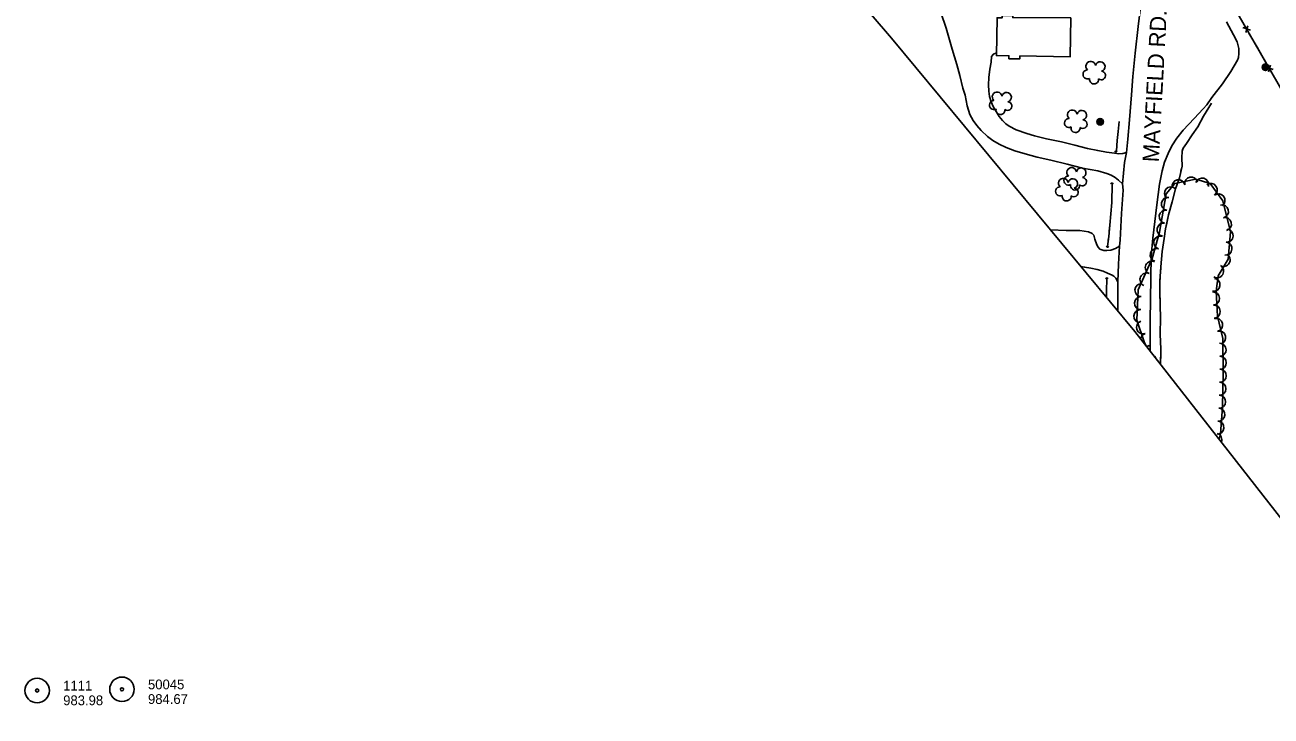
# Model space of a CAD drawing. Extents: x 353423 to 364002, y 127000 to 201942.
# Drawn here: x 356703 to 357469, y 134404 to 134829 of the extents above; entities that cross this region are included whole.
import ezdxf

# ---------------------------------------------------------------- set-up
doc = ezdxf.new("R2010")
doc.units = 0
for name, color, linetype in [('E_DTM_SlopeBottom', 7, 'Continuous'), ('E_DTM_SlopeTop', 7, 'Continuous'), ('E_FEN_Generic', 7, 'Continuous'), ('E_LAND_BrushLine', 7, 'Continuous'), ('E_MISCPROP', 7, 'Continuous'), ('E_RDWY_AsphConc', 7, 'Continuous'), ('E_RDWY_Gravel', 7, 'Continuous'), ('E_RW_IP', 7, 'Continuous'), ('E_STRUCT_WingWall', 7, 'Continuous'), ('E_WTR_FlowLine', 7, 'Continuous')]:
    doc.layers.add(name, color=color, linetype=linetype)

msp = doc.modelspace()

# ---------------------------------------------------------------- linework, layer by layer
at = {"layer": 'E_DTM_SlopeBottom'}
for p, q in [((357456.04, 134825.55), (357451.37, 134827.15)), ((357453.14, 134824.08), (357454.49, 134828.08)), ((357469.96, 134801.42), (357465.3, 134803.02)), ((357467.07, 134799.95), (357468.42, 134803.95))]:
    msp.add_line(p, q, dxfattribs=at)
for points in [[(357746.81, 134404.35), (357704.25, 134463.37), (357646.07, 134541.07), (357599.43, 134604.83), (357559.68, 134657.67), (357521.7, 134708.64), (357480.05, 134780.45), (357448.29, 134835.48), (357398.42, 134896.02), (357357.23, 134944.19), (357299.64, 135012.53), (357238.04, 135085.86), (357191.74, 135137.71), (357148.42, 135186.77), (357116.33, 135222.96), (357071.29, 135272.31), (357040.14, 135306.75), (357007.93, 135341.38)], [(357460.09, 134815.05), (357455.11, 134823.67)], [(357465.74, 134805.24), (357460.09, 134815.05)]]:
    msp.add_lwpolyline(points, dxfattribs=at)
for centre, major_axis, ratio, start_param, end_param in [((357373.66, 134752.11), (-0.34, -1.28), 0.626074, 5.356084, 7.210314), ((357370.83, 134730.28), (0.23, 1.35), 0.716546, 5.356056, 7.210287), ((357368.37, 134693.69), (-0.2, -1.41), 0.672824, 5.356084, 7.210314), ((357367.77, 134671.83), (0.08, 1.63), 0.539577, 5.356084, 7.210314)]:
    msp.add_ellipse(centre, major_axis=major_axis, ratio=ratio, start_param=start_param, end_param=end_param, dxfattribs=at)
at = {"layer": 'E_DTM_SlopeTop'}
for points in [[(357388.44, 134839.57), (357387.01, 134827.75), (357385.26, 134811.36), (357383.89, 134797.14), (357383.02, 134785.85), (357381.71, 134770.52), (357380.73, 134758.61), (357379.93, 134750.33), (357378.74, 134744.21), (357377.49, 134731.14), (357377.84, 134727.25), (357376.93, 134712.94), (357376.04, 134696.53), (357375.7, 134692.9), (357375.11, 134681.73), (357374.5, 134671), (357374.53, 134657.79), (357374.5, 134653.13)], [(357394.56, 134628.26), (357394.56, 134646.97), (357394.85, 134673.44), (357395.03, 134686.65), (357396.02, 134697.78), (357398.46, 134718.24), (357400.12, 134730.92), (357401.78, 134739.22), (357403.28, 134744.43), (357405.49, 134749.82), (357407.76, 134754.47), (357410.78, 134759.3), (357414.83, 134764.11), (357421.54, 134771.25), (357427.03, 134777.3), (357429.2, 134779.6), (357432.33, 134784.26), (357438.79, 134792.56), (357443.95, 134800.19), (357448.09, 134807.18), (357448.76, 134808.78), (357448.94, 134811.13), (357448.9, 134814.31), (357447.85, 134818.26), (357445.73, 134822.57), (357441.4, 134830.7)]]:
    msp.add_lwpolyline(points, dxfattribs=at)
at = {"layer": 'E_FEN_Generic'}
msp.add_lwpolyline([(357436.74, 134574.36), (357437.64, 134577.73), (357438.82, 134594.3), (357439.37, 134615.35), (357439.17, 134636.18), (357435.82, 134649.89), (357434.9, 134665.2), (357436.3, 134674.58), (357442.28, 134685), (357443.71, 134701.65), (357439.17, 134720.77), (357431.27, 134731.46), (357422.42, 134734.09), (357409.54, 134731.29), (357404.26, 134724.99), (357400.25, 134701.47), (357395.69, 134685.23), (357387.01, 134666.13), (357386.27, 134647.4), (357390.8, 134634.14), (357392.22, 134631.26)], dxfattribs=at)
for centre, radius, start, end in [((357357.94, 134803.37), 2.97, 7.26141, 228.49529), ((357363.79, 134803.14), 2.97, 284.91223, 167.8855), ((357355.98, 134798.36), 2.78, 90.2323, 298.00529), ((357360, 134795.28), 2.78, 166.90931, 7.92036), ((357364.45, 134797.65), 2.61, 229.61746, 87.55007), ((357300.45, 134784.56), 2.97, 7.26141, 228.49529), ((357306.3, 134784.33), 2.97, 284.91223, 167.8855), ((357298.49, 134779.56), 2.78, 90.2323, 298.00529), ((357306.95, 134778.85), 2.61, 229.61746, 87.55007), ((357302.51, 134776.47), 2.78, 166.90931, 7.92036), ((357344.63, 134768.51), 2.78, 90.2323, 298.00529), ((357346.59, 134773.51), 2.97, 7.26141, 228.49529), ((357352.43, 134773.29), 2.97, 284.91223, 167.8855), ((357348.64, 134765.43), 2.78, 166.90931, 7.92036), ((357353.09, 134767.8), 2.61, 229.61746, 87.55007), ((357346.23, 134738.17), 2.97, 7.26141, 228.49529), ((357352.08, 134737.94), 2.97, 284.91223, 167.8855), ((357341.1, 134731.53), 2.97, 7.26141, 228.49529), ((357344.27, 134733.16), 2.78, 90.2323, 298.00529), ((357346.95, 134731.3), 2.97, 284.91223, 167.8855), ((357352.74, 134732.46), 2.61, 229.61746, 87.55007), ((357411.85, 134729.65), 4, 12.27553, 192.2602), ((357419.67, 134731.35), 4, 12.27553, 192.2602), ((357426.36, 134730.74), 4, 343.47008, 163.45476), ((357339.14, 134726.53), 2.78, 90.2323, 298.00529), ((357348.29, 134730.08), 2.78, 166.90931, 7.92036), ((357347.61, 134725.82), 2.61, 229.61746, 87.55007), ((357407.23, 134725.28), 4, 50.02031, 230.00499), ((357431.66, 134727.41), 4, 306.43791, 126.42258), ((357343.16, 134723.44), 2.78, 166.90931, 7.92036), ((357405.34, 134718.86), 4, 80.34236, 260.32704), ((357436.41, 134720.97), 4, 306.43791, 126.42258), ((357438.56, 134714.26), 4, 283.35437, 103.33905), ((357403.99, 134710.97), 4, 80.34236, 260.32704), ((357440.41, 134706.47), 4, 283.35437, 103.33905), ((357402.65, 134703.09), 4, 80.34236, 260.32704), ((357441.4, 134699.29), 4, 265.10079, 85.08547), ((357400.65, 134695.13), 4, 74.32817, 254.31285), ((357440.72, 134691.32), 4, 265.10079, 85.08547), ((357398.48, 134687.43), 4, 74.32817, 254.31285), ((357439.55, 134684.45), 4, 240.17306, 60.15774), ((357395.48, 134679.69), 4, 65.56841, 245.55309), ((357435.57, 134677.51), 4, 240.17306, 60.15774), ((357392.17, 134672.41), 4, 65.56841, 245.55309), ((357433.37, 134669.13), 4, 261.49924, 81.48392), ((357389.1, 134665.9), 4, 87.74334, 267.72802), ((357433.07, 134660.75), 4, 273.44352, 93.4282), ((357388.78, 134657.91), 4, 87.74334, 267.72802), ((357433.55, 134652.76), 4, 273.44352, 93.4282), ((357388.47, 134649.91), 4, 87.74334, 267.72802), ((357390, 134642.96), 4, 108.85885, 288.84352), ((357434.97, 134644.54), 4, 283.75563, 103.74031), ((357392.58, 134635.39), 4, 108.85885, 173.19028), ((357436.87, 134636.77), 4, 283.75563, 103.74031), ((357392.58, 134635.39), 4, 262.89689, 288.84353), ((357395.86, 134628.61), 4, 121.46991, 146.02388), ((357437.15, 134629.28), 4, 270.54592, 90.53059), ((357395.86, 134628.61), 4, 290.06329, 301.45459), ((357400.03, 134621.79), 4, 121.46991, 132.60292), ((357437.22, 134621.28), 4, 270.54592, 90.53059), ((357437.22, 134613.36), 4, 268.50051, 88.48519), ((357437.01, 134605.36), 4, 268.50051, 88.48519), ((357436.8, 134597.37), 4, 268.50051, 88.48519), ((357436.37, 134589.48), 4, 265.93674, 85.92142), ((357435.81, 134581.5), 4, 265.93674, 85.92142), ((357434.49, 134574.04), 4, 337.48606, 75.15008)]:
    msp.add_arc(centre, radius, start, end, dxfattribs=at)
at = {"layer": 'E_LAND_BrushLine'}
for centre, radius in [((357465.22, 134802.73), 2.02), ((357465.2, 134802.72), 1.52), ((357465.24, 134802.73), 1.01), ((357465.23, 134802.73), 0.502), ((357363.68, 134769.26), 2.02), ((357363.67, 134769.25), 1.52), ((357363.71, 134769.26), 1.01), ((357363.7, 134769.26), 0.502)]:
    msp.add_circle(centre, radius, dxfattribs=at)
at = {"layer": 'E_MISCPROP'}
for points in [[(357265.85, 134836.31), (357269.19, 134826.84), (357272.85, 134813.82), (357275.62, 134804.49), (357277.55, 134797.63), (357279.49, 134789.94), (357280.74, 134785.53), (357282.05, 134778.96), (357283.61, 134773.64), (357285.7, 134769.99), (357287.9, 134767.04), (357290.58, 134763.91), (357294.49, 134760.3), (357297.73, 134757.86), (357301.76, 134755.61), (357306.08, 134753.47), (357311.4, 134751.43), (357317.75, 134749.61), (357325.14, 134747.6), (357333.47, 134745.6), (357343.56, 134743.15), (357352.92, 134740.8), (357362.33, 134739.14), (357367.87, 134737.55), (357370.57, 134736.57), (357373.05, 134735.14), (357375.11, 134733.4), (357377.49, 134731.14)], [(357379.93, 134750.33), (357377.57, 134749.81), (357375.13, 134749.67), (357372.61, 134749.94), (357367.72, 134750.57), (357362.25, 134751.58), (357355.96, 134752.86), (357348.25, 134754.96), (357339.96, 134756.87), (357330.84, 134758.81), (357323.45, 134760.57), (357318.66, 134762.02), (357312.11, 134764.38), (357307.88, 134766.64), (357305.81, 134768.1), (357303.79, 134770.09), (357301.75, 134772.58), (357299.77, 134775.48), (357298.07, 134778.63), (357296.83, 134781.51), (357295.76, 134784.88), (357295.31, 134788.12), (357295.16, 134791.92), (357295.36, 134796.38), (357295.95, 134801.52), (357296.76, 134805.8), (357297.07, 134809.42), (357298.21, 134810.71), (357300.08, 134811.56)], [(357375.7, 134692.9), (357373.22, 134691.44), (357370.22, 134690.45), (357367.9, 134690.18), (357365.96, 134690.19), (357363.55, 134691.12), (357362.59, 134692.22), (357361.63, 134693.64), (357360.44, 134697.15), (357359.77, 134699.68), (357358.8, 134700.62), (357356.48, 134701.71), (357351.33, 134702.51), (357342.79, 134702.57), (357333.23, 134702.85)], [(357351.95, 134680.31), (357354.21, 134680.05), (357358.03, 134679.28), (357361.81, 134678.52), (357365.5, 134677.48), (357368.2, 134676.37), (357371.02, 134675.1), (357372.24, 134674.41), (357373.28, 134673.18), (357374.5, 134671)]]:
    msp.add_lwpolyline(points, dxfattribs=at)
at = {"layer": 'E_RDWY_AsphConc'}
for centre, radius in [((356710.79, 134420.02), 7.5), ((356710.79, 134420.02), 7.5), ((356762.88, 134420.79), 7.5), ((356762.88, 134420.79), 7.5), ((356710.79, 134420.02), 0.96), ((356710.79, 134420.02), 0.96), ((356762.88, 134420.79), 0.96), ((356762.88, 134420.79), 0.96)]:
    msp.add_circle(centre, radius, dxfattribs=at)
at = {"layer": 'E_RDWY_Gravel'}
msp.add_lwpolyline([(357561.26, 134412.64), (357492.25, 134503.43), (357384.94, 134640.56), (357235.52, 134820.57), (357113.15, 134963.23), (357002.36, 135091.01), (356876.53, 135226.25), (356878.1, 135336.28)], dxfattribs=at)
at = {"layer": 'E_STRUCT_WingWall'}
for points in [[(357432.07, 134780.64), (357427.24, 134772.79), (357423.68, 134766.19), (357420.28, 134761.16), (357416.72, 134755.89), (357414.66, 134753.05), (357414.03, 134751.17), (357413.93, 134747.2), (357414.04, 134742.08), (357412.4, 134734.81), (357409.96, 134728.18), (357407.89, 134720.18), (357405.73, 134712.02), (357403.9, 134703.6), (357403, 134697.68), (357401.92, 134689.61), (357401.05, 134680.09), (357400.49, 134671.43), (357400.41, 134665.03), (357400.67, 134656.15), (357400.73, 134649.12), (357400.63, 134638.8), (357400.92, 134629.58), (357400.87, 134620.2)], [(357432.07, 134780.64), (357427.24, 134772.79), (357423.68, 134766.19), (357420.28, 134761.16), (357416.8, 134756.01)], [(357375.35, 134769.36), (357374.74, 134763.3), (357374.27, 134757.74), (357373.69, 134751.43)], [(357375.35, 134769.36), (357374.74, 134763.3), (357374.27, 134757.74), (357373.69, 134751.43)], [(357414.55, 134752.72), (357414.03, 134751.17), (357414.02, 134750.8)], [(357413.76, 134740.84), (357413.32, 134738.89)], [(357413.94, 134746.81), (357413.98, 134744.81)], [(357412.44, 134734.98), (357412.4, 134734.81), (357409.96, 134728.18), (357407.89, 134720.18), (357405.73, 134712.02), (357404.66, 134707.08)], [(357371.16, 134730.97), (357370.83, 134719.7), (357369.72, 134705.81), (357368.99, 134698.73), (357368.26, 134692.59)], [(357371.16, 134730.97), (357370.83, 134719.7), (357369.72, 134705.81), (357369.33, 134702.04)], [(357404.66, 134707.08), (357403.9, 134703.6), (357403, 134697.68), (357401.92, 134689.61), (357401.05, 134680.09), (357400.94, 134678.35)], [(357368.91, 134698.06), (357368.67, 134696.08)], [(357367.78, 134672.86), (357367.62, 134665.43), (357367.6, 134661.45)], [(357367.78, 134672.86), (357367.62, 134665.43), (357367.6, 134661.45)], [(357400.68, 134674.36), (357400.55, 134672.36)], [(357400.45, 134668.36), (357400.42, 134666.36)], [(357400.49, 134662.36), (357400.54, 134660.37)], [(357400.66, 134656.37), (357400.67, 134656.15), (357400.73, 134649.12), (357400.63, 134638.8), (357400.92, 134629.58), (357400.91, 134627.37)], [(357400.91, 134627.37), (357400.87, 134620.2)]]:
    msp.add_lwpolyline(points, dxfattribs=at)
at = {"layer": 'E_WTR_FlowLine'}
msp.add_lwpolyline([(357345.8, 134833.05), (357345.38, 134809.18), (357314.42, 134809.73), (357314.39, 134807.89), (357307.68, 134808.01), (357307.72, 134809.8), (357300.05, 134809.94), (357300.46, 134833.13), (357303.47, 134833.07), (357303.49, 134834.45), (357310.11, 134834.33), (357310.04, 134833.24)], close=True, dxfattribs=at)

# ---------------------------------------------------------------- texts
at = {"layer": 'E_RDWY_AsphConc'}
for s, p in [('50045', (356778.88, 134420.79)), ('50045', (356778.88, 134420.79)), ('1111', (356726.79, 134420.02)), ('1111', (356726.79, 134420.02)), ('983.98', (356726.79, 134411.02)), ('983.98', (356726.79, 134411.02)), ('984.67', (356778.88, 134411.79)), ('984.67', (356778.88, 134411.79))]:
    msp.add_text(s, height=6, dxfattribs=at).set_placement(p)
at = {"layer": 'E_RW_IP'}
msp.add_text('MAYFIELD RD.', height=10, rotation=86.9097, dxfattribs=at).set_placement((357399.71, 134744.25))

doc.saveas('drawing.dxf')
